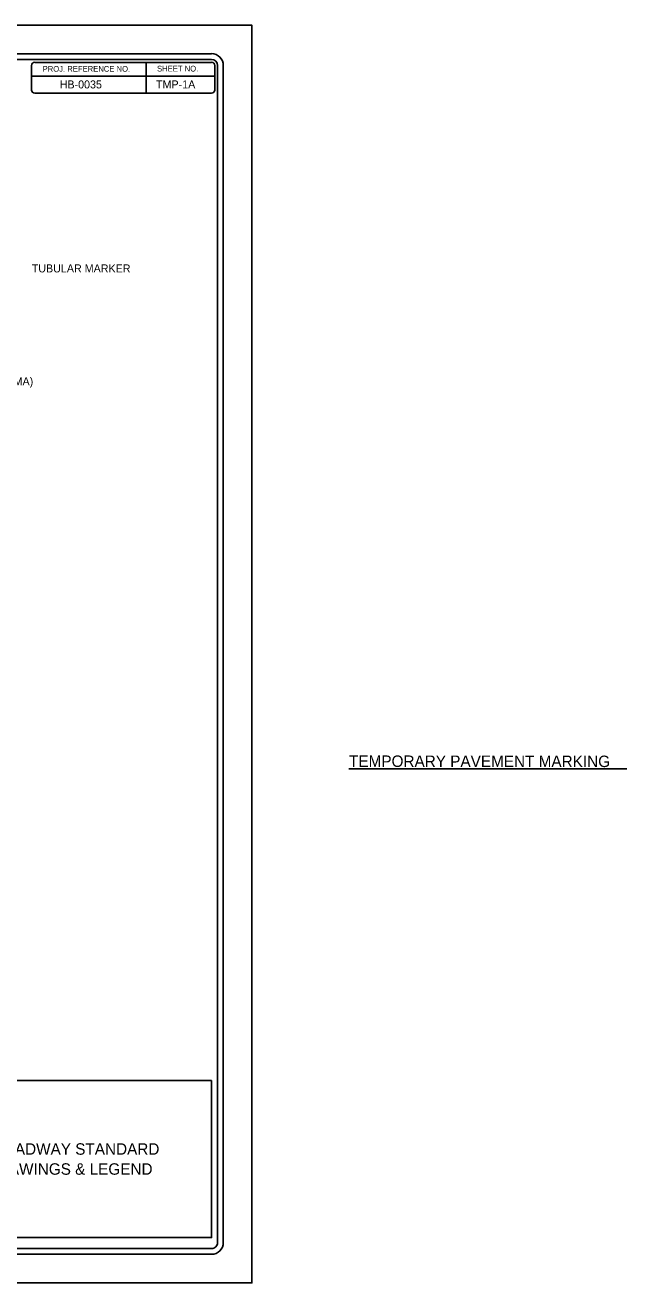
# Model space of a CAD drawing. Extents: x 198 to 2213, y -571 to 529.
# Drawn here: x 1688 to 2213, y -571 to 529 of the extents above; entities that cross this region are included whole.
import ezdxf

# ---------------------------------------------------------------- set-up
doc = ezdxf.new("R2010")
doc.units = 0
doc.layers.add('Sheet Data Field CELL', color=7, linetype='Continuous')
doc.layers.add('Sheet PE Seal CELL', color=7, linetype='Continuous')

msp = doc.modelspace()

# ---------------------------------------------------------------- linework, layer by layer
at = {"layer": 'Sheet Data Field CELL'}
for points in [[(197.7, -570.9), (1885.7, -570.9), (1885.7, 529.1), (197.7, 529.1)], [(197.7, 529.1), (1885.7, 529.1), (1885.7, -570.9), (197.7, -570.9)]]:
    msp.add_lwpolyline(points, close=True, dxfattribs=at)
at = {"layer": 'Sheet PE Seal CELL'}
for p, q in [((1850.4, 504.1), (370.9, 504.1)), ((1850.4, 499.1), (938.4, 499.1)), ((1695.9, 496.6), (1850.4, 496.6)), ((1793.2, 484.6), (1793.2, 496.6)), ((1693.2, 472.4), (1693.2, 493.9)), ((1693.2, 484.6), (1853.2, 484.6)), ((1793.2, 469.6), (1793.2, 484.6)), ((1853.2, 493.9), (1853.2, 491.7)), ((1853.2, 491.7), (1853.2, 472.4)), ((1855.7, -535.6), (1855.7, 493.9)), ((1860.7, -535.6), (1860.7, 493.9)), ((1695.9, 469.6), (1850.4, 469.6)), ((1970.3, -121.3), (2213.3, -121.4)), ((370.9, -545.9), (1850.4, -545.9)), ((938.4, -540.9), (1850.4, -540.9))]:
    msp.add_line(p, q, dxfattribs=at)
msp.add_lwpolyline([(1850.5, -393.8), (1614.5, -393.8), (1614.5, -531.3), (1850.5, -531.3)], close=True, dxfattribs=at)
for centre, radius, start, end in [((1695.9, 493.9), 2.79, 90.0005, 181.1644), ((1850.4, 493.9), 10.3, 0.0001, 89.9995), ((1850.4, 493.9), 5.29, 0.0001, 89.9995), ((1850.4, 493.9), 2.79, 0.0001, 89.9995), ((1695.9, 472.4), 2.79, 180.0001, 270.0005), ((1850.4, 472.4), 2.79, 270.0005, 359.9999), ((1850.4, -535.6), 10.3, 270, 0.0001), ((1850.4, -535.6), 5.29, 270, 0.0001), ((1850.4, -535.6), 5.29, 270, 0.0001)]:
    msp.add_arc(centre, radius, start, end, dxfattribs=at)

# ---------------------------------------------------------------- texts
for s, height, rotation, p in [('PROJ. REFERENCE NO.', 4.999, 0.0006, (1702.8, 488.4)), ('SHEET NO.', 5, 0.0006, (1802.8, 488.6)), ('TUBULAR MARKER', 7, 359.9598, (1693.3, 312.9)), ('TRUCK MOUNTED ATTENUATOR (TMA)', 7, 359.9598, (1517.8, 214.2)), ('TEMPORARY PAVEMENT MARKING ', 10, 359.9598, (1970.6, -119.6))]:
    msp.add_text(s, height=height, rotation=rotation, dxfattribs=at).set_placement(p)
for s, height, p in [('HB-0035', 7, (1717.7, 473.8)), ('TMP-1A ', 7, (1801.9, 473.8)), ('ROADWAY STANDARD ', 10, (1658.5, -458.8)), ('DRAWINGS & LEGEND', 10, (1654, -476.3))]:
    msp.add_text(s, height=height, dxfattribs=at).set_placement(p)

doc.saveas('drawing.dxf')
